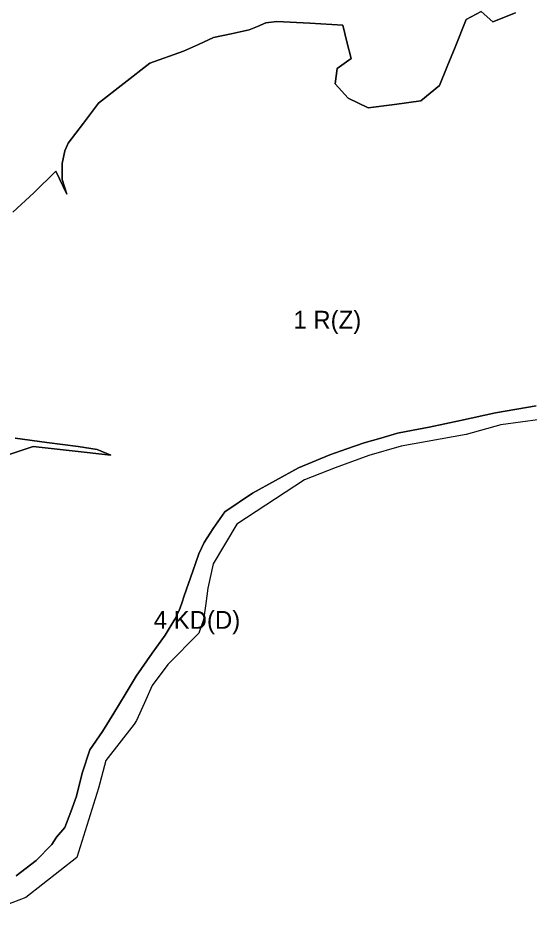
# Model space of a CAD drawing. Extents: x 7423691 to 7425475, y 5552085 to 5554331.
# Drawn here: x 7424789.8 to 7425018, y 5552520 to 5552921.5 of the extents above; entities that cross this region are included whole.
import ezdxf

# ---------------------------------------------------------------- set-up
doc = ezdxf.new("R2010")
doc.units = 0
doc.layers.add('linie_rozgraniczajace', color=7, linetype='Continuous')
doc.layers.add('oznaczenia_przeznaczen', color=7, linetype='Continuous')

msp = doc.modelspace()

# ---------------------------------------------------------------- linework, layer by layer
at = {"layer": 'linie_rozgraniczajace'}
for points in [[(7425011.96, 5552923.77), (7425001.77, 5552919.8), (7424996.57, 5552924.37), (7424989.86, 5552920.81), (7424985.02, 5552908.36), (7424981.51, 5552899.8), (7424978, 5552891.24), (7424969.72, 5552884.41), (7424957.91, 5552882.82), (7424946.1, 5552881.22), (7424937.3, 5552885.56), (7424931.43, 5552891.97), (7424932.3, 5552898.83), (7424938.56, 5552903.39), (7424936.67, 5552910.82), (7424934.78, 5552918.24), (7424920.08, 5552919.09), (7424905.37, 5552919.94), (7424900.53, 5552919.24), (7424896.76, 5552917.68), (7424892.99, 5552916.12), (7424885.02, 5552914.39), (7424877.06, 5552912.67), (7424870.4, 5552909.62), (7424863.75, 5552906.58), (7424848.68, 5552901.23), (7424837.19, 5552892.34), (7424825.7, 5552883.45), (7424818.98, 5552874.49), (7424812.25, 5552865.53), (7424810.72, 5552862.01), (7424809.54, 5552856.41), (7424809.52, 5552849.3), (7424811.59, 5552842.68), (7424806.76, 5552852.91), (7424796.93, 5552843.32), (7424787.47, 5552834.64)], [(7424787.47, 5552834.64), (7424796.93, 5552843.32), (7424806.76, 5552852.91), (7424811.59, 5552842.68), (7424809.52, 5552849.3), (7424809.54, 5552856.41), (7424810.72, 5552862.01), (7424812.25, 5552865.53), (7424818.98, 5552874.49), (7424825.7, 5552883.45), (7424837.19, 5552892.34), (7424848.68, 5552901.23), (7424863.75, 5552906.58), (7424870.4, 5552909.62), (7424877.06, 5552912.67), (7424885.02, 5552914.39), (7424892.99, 5552916.12), (7424896.76, 5552917.68), (7424900.53, 5552919.24), (7424905.37, 5552919.94), (7424920.08, 5552919.09), (7424934.78, 5552918.24), (7424936.67, 5552910.82), (7424938.56, 5552903.39), (7424932.3, 5552898.83), (7424931.43, 5552891.97), (7424937.3, 5552885.56), (7424946.1, 5552881.22), (7424957.91, 5552882.82), (7424969.72, 5552884.41), (7424978, 5552891.24), (7424981.51, 5552899.8), (7424985.02, 5552908.36), (7424989.86, 5552920.81), (7424996.57, 5552924.37), (7425001.77, 5552919.8), (7425011.96, 5552923.77)], [(7425021.19, 5552748.05), (7425003.05, 5552744.91), (7424987.44, 5552741.54), (7424973.38, 5552738.58), (7424966.32, 5552737.18), (7424959.26, 5552735.79), (7424951.82, 5552733.69), (7424944.39, 5552731.59), (7424936.7, 5552728.9), (7424929.01, 5552726.21), (7424915.05, 5552720.31), (7424904.74, 5552714.67), (7424894.44, 5552709.02), (7424882.21, 5552700.63), (7424876.96, 5552693.28), (7424873, 5552687.05), (7424870.55, 5552681.95), (7424869.23, 5552678.1), (7424867.9, 5552674.24), (7424865.97, 5552668.68), (7424864.04, 5552663.11), (7424862.93, 5552659.82), (7424861.82, 5552656.53), (7424859.89, 5552652.69), (7424855.57, 5552645.57), (7424849.7, 5552637.48), (7424842.61, 5552627.28), (7424837.63, 5552618.98), (7424832.64, 5552610.69), (7424827.56, 5552602.42), (7424821.94, 5552594.3), (7424818.44, 5552583.82), (7424815.94, 5552573.61), (7424813.39, 5552566.65), (7424810.77, 5552559.53), (7424806.99, 5552555.22), (7424804.89, 5552552), (7424797.91, 5552544.77), (7424788.94, 5552537.9)], [(7424788.94, 5552537.9), (7424797.91, 5552544.77), (7424804.89, 5552552), (7424806.99, 5552555.22), (7424810.77, 5552559.53), (7424813.39, 5552566.65), (7424815.94, 5552573.61), (7424818.44, 5552583.82), (7424821.94, 5552594.3), (7424827.56, 5552602.42), (7424832.64, 5552610.69), (7424837.63, 5552618.98), (7424842.61, 5552627.28), (7424849.7, 5552637.48), (7424855.57, 5552645.57), (7424859.89, 5552652.69), (7424861.82, 5552656.53), (7424862.93, 5552659.82), (7424864.04, 5552663.11), (7424865.97, 5552668.68), (7424867.9, 5552674.24), (7424869.23, 5552678.1), (7424870.55, 5552681.95), (7424873, 5552687.05), (7424876.96, 5552693.28), (7424882.21, 5552700.63), (7424894.44, 5552709.02), (7424904.74, 5552714.67), (7424915.05, 5552720.31), (7424929.01, 5552726.21), (7424936.7, 5552728.9), (7424944.39, 5552731.59), (7424951.82, 5552733.69), (7424959.26, 5552735.79), (7424966.32, 5552737.18), (7424973.38, 5552738.58), (7424987.44, 5552741.54), (7425003.05, 5552744.91), (7425021.19, 5552748.05)], [(7425022.98, 5552742.04), (7425005.4, 5552739.51), (7424989.92, 5552735.26), (7424960.85, 5552730.04), (7424946.47, 5552725.88), (7424931.43, 5552720.34), (7424917.78, 5552714.93), (7424887.52, 5552695.21)], [(7424788.53, 5552733.56), (7424802.62, 5552731.75), (7424816.7, 5552729.95), (7424825.14, 5552728.49), (7424831.32, 5552726.02), (7424813.96, 5552727.99), (7424796.59, 5552729.96), (7424782.73, 5552725.32)], [(7424782.73, 5552725.32), (7424796.59, 5552729.96), (7424813.96, 5552727.99), (7424831.32, 5552726.02), (7424825.14, 5552728.49), (7424816.7, 5552729.95), (7424802.62, 5552731.75), (7424788.53, 5552733.56)], [(7424887.52, 5552695.21), (7424877, 5552677.5), (7424874.55, 5552666.57), (7424873.65, 5552659.77), (7424872.66, 5552652.39), (7424870.55, 5552646.47), (7424856.75, 5552632.4), (7424849.71, 5552623.09), (7424846.22, 5552615.24), (7424842.74, 5552607.38), (7424841.61, 5552605.76), (7424829.04, 5552589.49), (7424825.79, 5552577.17), (7424816.07, 5552546.19), (7424793.23, 5552528.28), (7424771.24, 5552520)]]:
    msp.add_lwpolyline(points, dxfattribs=at)

# ---------------------------------------------------------------- texts
at = {"layer": 'oznaczenia_przeznaczen'}
for s, p in [('1 R(Z)', (7424912.75, 5552782.55)), ('4 KD(D)', (7424850.39, 5552648.39))]:
    msp.add_text(s, height=8, dxfattribs=at).set_placement(p)

doc.saveas('drawing.dxf')
